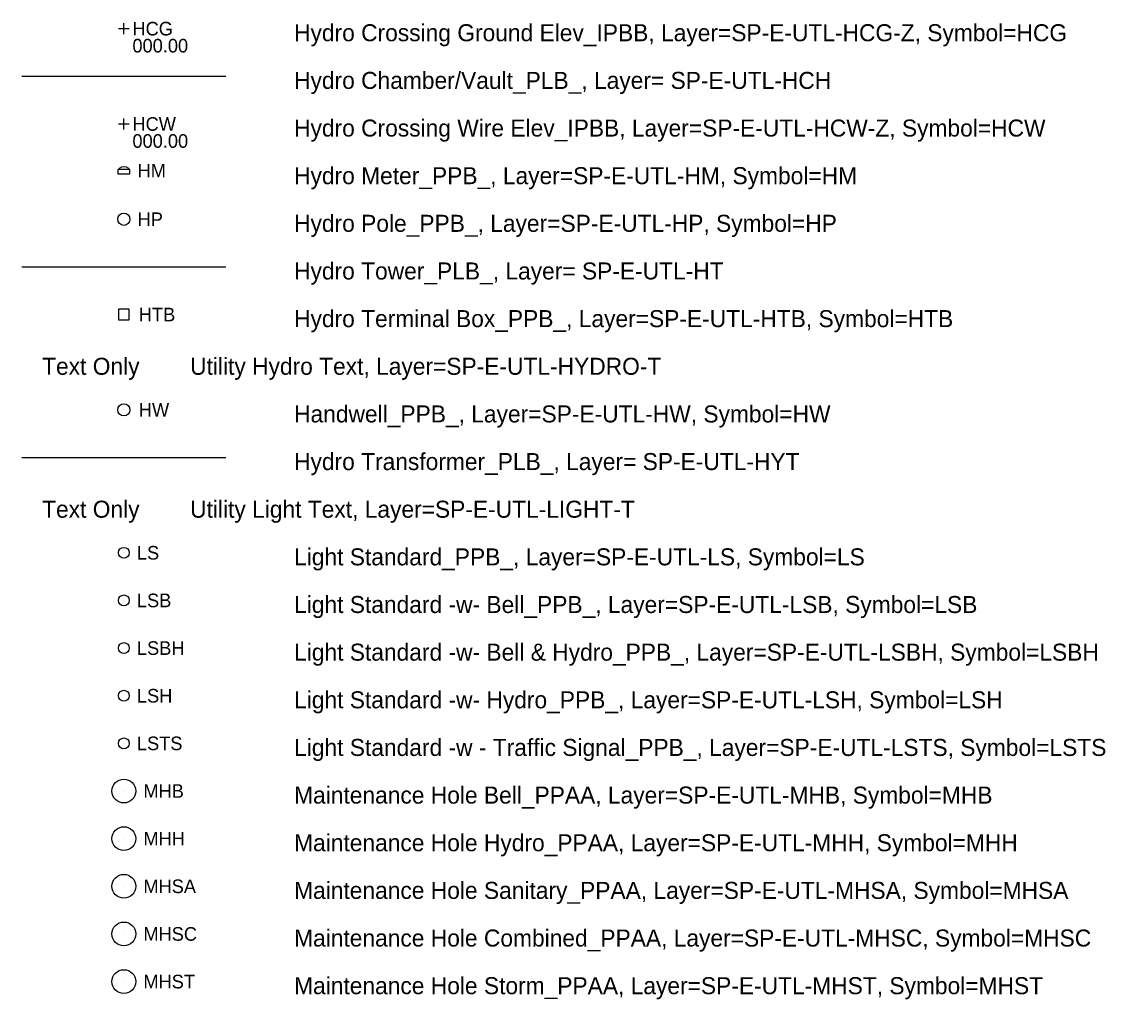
# Model space of a CAD drawing. Extents: x 500528 to 502626, y 4210261 to 4212624.
# Drawn here: x 501386.5 to 501545.7, y 4211000 to 4211143.6 of the extents above; entities that cross this region are included whole.
import ezdxf

# ---------------------------------------------------------------- set-up
doc = ezdxf.new("R2010")
doc.units = 0
for name, color, linetype in [('SP-E-UTL-BELL-T', 7, 'Continuous'), ('SP-E-UTL-COMB-T', 7, 'Continuous'), ('SP-E-UTL-HCG-Z', 7, 'Continuous'), ('SP-E-UTL-HCH', 7, 'Continuous'), ('SP-E-UTL-HCW-Z', 7, 'Continuous'), ('SP-E-UTL-HM', 7, 'Continuous'), ('SP-E-UTL-HP', 7, 'Continuous'), ('SP-E-UTL-HT', 7, 'Continuous'), ('SP-E-UTL-HTB', 7, 'Continuous'), ('SP-E-UTL-HW', 7, 'Continuous'), ('SP-E-UTL-HYDRO-T', 7, 'Continuous'), ('SP-E-UTL-HYT', 7, 'Continuous'), ('SP-E-UTL-LIGHT-T', 7, 'Continuous'), ('SP-E-UTL-LS', 7, 'Continuous'), ('SP-E-UTL-LSB', 7, 'Continuous'), ('SP-E-UTL-LSBH', 7, 'Continuous'), ('SP-E-UTL-LSH', 7, 'Continuous'), ('SP-E-UTL-LSTS', 7, 'Continuous'), ('SP-E-UTL-MHB', 7, 'Continuous'), ('SP-E-UTL-MHH', 7, 'Continuous'), ('SP-E-UTL-MHSA', 7, 'Continuous'), ('SP-E-UTL-MHSC', 7, 'Continuous'), ('SP-E-UTL-MHST', 7, 'Continuous'), ('SP-E-UTL-SAN-ST-COMB-T', 7, 'Continuous'), ('SP-E-UTL-SAN-T', 7, 'Continuous'), ('SP-E-UTL-STORM-T', 7, 'Continuous'), ('SP-E-UTL-T', 7, 'Continuous')]:
    doc.layers.add(name, color=color, linetype=linetype)

# ---------------------------------------------------------------- blocks, each defined once
blk = doc.blocks.new('HCG')
at = {"layer": 'SP-E-UTL-HCG-Z'}
for points in [[(-0.08, 0), (0.08, 0)], [(0, -0.08), (0, 0.08)]]:
    blk.add_lwpolyline(points, dxfattribs=at)
at = {"layer": 'SP-E-UTL-HYDRO-T'}
for s, p in [('HCG', (0.126, -0.1)), ('000.00', (0.126, -0.35))]:
    blk.add_text(s, height=0.2, dxfattribs=at).set_placement(p)
blk = doc.blocks.new('HCW')
at = {"layer": 'SP-E-UTL-HCW-Z'}
for points in [[(-0.08, 0), (0.08, 0)], [(0, -0.08), (0, 0.08)]]:
    blk.add_lwpolyline(points, dxfattribs=at)
at = {"layer": 'SP-E-UTL-HYDRO-T'}
for s, p in [('HCW', (0.126, -0.1)), ('000.00', (0.126, -0.35))]:
    blk.add_text(s, height=0.2, dxfattribs=at).set_placement(p)
blk = doc.blocks.new('HM')
at = {"layer": 'SP-E-UTL-HM'}
for p, q in [((-0.071, 0.048), (-0.071, 0.031)), ((0.071, 0.031), (0.071, 0.048))]:
    blk.add_line(p, q, dxfattribs=at)
blk.add_lwpolyline([(-0.09, -0.031), (0.09, -0.031), (0.09, 0.031), (-0.09, 0.031)], close=True, dxfattribs=at)
blk.add_arc((0, -0.049), 0.12, 53.7956, 126.2044, dxfattribs=at)
at = {"layer": 'SP-E-UTL-HYDRO-T'}
blk.add_text('HM', height=0.2, dxfattribs=at).set_placement((0.202, -0.086))
blk = doc.blocks.new('HP')
at = {"layer": 'SP-E-UTL-HP'}
blk.add_lwpolyline([(0, 0), (0, 0)], dxfattribs=at)
blk.add_circle((0, 0), 0.09, dxfattribs=at)
at = {"layer": 'SP-E-UTL-HYDRO-T'}
blk.add_text('HP', height=0.2, dxfattribs=at).set_placement((0.202, -0.1))
blk = doc.blocks.new('HTB')
at = {"layer": 'SP-E-UTL-HTB'}
for points in [[(-0.08, 0.08), (-0.08, -0.08), (0.08, -0.08), (0.08, 0.08), (-0.08, 0.08)], [(0, 0), (0, 0)]]:
    blk.add_lwpolyline(points, dxfattribs=at)
at = {"layer": 'SP-E-UTL-HYDRO-T'}
blk.add_text('HTB', height=0.2, dxfattribs=at).set_placement((0.22, -0.1))
blk = doc.blocks.new('HW')
at = {"layer": 'SP-E-UTL-HW'}
blk.add_lwpolyline([(0, 0), (0, 0)], dxfattribs=at)
blk.add_circle((0, 0), 0.09, dxfattribs=at)
at = {"layer": 'SP-E-UTL-T'}
blk.add_text('HW', height=0.2, dxfattribs=at).set_placement((0.22, -0.1))
blk = doc.blocks.new('LS')
at = {"layer": 'SP-E-UTL-LS'}
blk.add_lwpolyline([(0, 0), (0, 0)], dxfattribs=at)
blk.add_circle((0, 0), 0.08, dxfattribs=at)
at = {"layer": 'SP-E-UTL-LIGHT-T'}
blk.add_text('LS', height=0.2, dxfattribs=at).set_placement((0.192, -0.1))
blk = doc.blocks.new('LSB')
at = {"layer": 'SP-E-UTL-LSB'}
blk.add_lwpolyline([(0, 0), (0, 0)], dxfattribs=at)
blk.add_circle((0, 0), 0.08, dxfattribs=at)
at = {"layer": 'SP-E-UTL-COMB-T'}
blk.add_text('LSB', height=0.2, dxfattribs=at).set_placement((0.192, -0.1))
blk = doc.blocks.new('LSBH')
at = {"layer": 'SP-E-UTL-LSBH'}
blk.add_lwpolyline([(0, 0), (0, 0)], dxfattribs=at)
blk.add_circle((0, 0), 0.08, dxfattribs=at)
at = {"layer": 'SP-E-UTL-COMB-T'}
blk.add_text('LSBH', height=0.2, dxfattribs=at).set_placement((0.192, -0.1))
blk = doc.blocks.new('LSH')
at = {"layer": 'SP-E-UTL-LSH'}
blk.add_lwpolyline([(0, 0), (0, 0)], dxfattribs=at)
blk.add_circle((0, 0), 0.08, dxfattribs=at)
at = {"layer": 'SP-E-UTL-COMB-T'}
blk.add_text('LSH', height=0.2, dxfattribs=at).set_placement((0.192, -0.1))
blk = doc.blocks.new('LSTS')
at = {"layer": 'SP-E-UTL-LSTS'}
blk.add_lwpolyline([(0, 0), (0, 0)], dxfattribs=at)
blk.add_circle((0, 0), 0.08, dxfattribs=at)
at = {"layer": 'SP-E-UTL-COMB-T'}
blk.add_text('LSTS', height=0.2, dxfattribs=at).set_placement((0.192, -0.1))
blk = doc.blocks.new('MHB')
at = {"layer": 'SP-E-UTL-MHB'}
blk.add_lwpolyline([(0, 0), (0, 0)], dxfattribs=at)
blk.add_circle((0, 0), 0.175, dxfattribs=at)
at = {"layer": 'SP-E-UTL-BELL-T'}
blk.add_text('MHB', height=0.2, dxfattribs=at).set_placement((0.287, -0.1))
blk = doc.blocks.new('MHH')
at = {"layer": 'SP-E-UTL-MHH'}
blk.add_lwpolyline([(0, 0), (0, 0)], dxfattribs=at)
blk.add_circle((0, 0), 0.175, dxfattribs=at)
at = {"layer": 'SP-E-UTL-HYDRO-T'}
blk.add_text('MHH', height=0.2, dxfattribs=at).set_placement((0.287, -0.1))
blk = doc.blocks.new('MHSA')
at = {"layer": 'SP-E-UTL-MHSA'}
blk.add_lwpolyline([(0, 0), (0, 0)], dxfattribs=at)
blk.add_circle((0, 0), 0.175, dxfattribs=at)
at = {"layer": 'SP-E-UTL-SAN-T'}
blk.add_text('MHSA', height=0.2, dxfattribs=at).set_placement((0.287, -0.1))
blk = doc.blocks.new('MHSC')
at = {"layer": 'SP-E-UTL-MHSC'}
blk.add_lwpolyline([(0, 0), (0, 0)], dxfattribs=at)
blk.add_circle((0, 0), 0.175, dxfattribs=at)
at = {"layer": 'SP-E-UTL-SAN-ST-COMB-T'}
blk.add_text('MHSC', height=0.2, dxfattribs=at).set_placement((0.287, -0.1))
blk = doc.blocks.new('MHST')
at = {"layer": 'SP-E-UTL-MHST'}
blk.add_lwpolyline([(0, 0), (0, 0)], dxfattribs=at)
blk.add_circle((0, 0), 0.175, dxfattribs=at)
at = {"layer": 'SP-E-UTL-STORM-T'}
blk.add_text('MHST', height=0.2, dxfattribs=at).set_placement((0.287, -0.1))

msp = doc.modelspace()

# ---------------------------------------------------------------- linework, layer by layer
at = {"layer": 'SP-E-UTL-HCH'}
msp.add_line((501386.55, 4211135.59), (501416.55, 4211135.59), dxfattribs=at)
at = {"layer": 'SP-E-UTL-HT'}
msp.add_line((501386.55, 4211107.59), (501416.55, 4211107.59), dxfattribs=at)
at = {"layer": 'SP-E-UTL-HYT'}
msp.add_line((501386.55, 4211079.59), (501416.55, 4211079.59), dxfattribs=at)

# ---------------------------------------------------------------- block references
at = {"layer": 'SP-E-UTL-HCG-Z', "xscale": 10, "yscale": 10}
msp.add_blockref('HCG', (501401.55, 4211142.59), dxfattribs=at)
at = {"layer": 'SP-E-UTL-HCW-Z', "xscale": 10, "yscale": 10}
msp.add_blockref('HCW', (501401.55, 4211128.59), dxfattribs=at)
at = {"layer": 'SP-E-UTL-HM', "xscale": 10, "yscale": 10}
msp.add_blockref('HM', (501401.55, 4211121.59), dxfattribs=at)
at = {"layer": 'SP-E-UTL-HP', "xscale": 10, "yscale": 10}
msp.add_blockref('HP', (501401.55, 4211114.59), dxfattribs=at)
at = {"layer": 'SP-E-UTL-HTB', "xscale": 10, "yscale": 10}
msp.add_blockref('HTB', (501401.55, 4211100.59), dxfattribs=at)
at = {"layer": 'SP-E-UTL-HW', "xscale": 10, "yscale": 10}
msp.add_blockref('HW', (501401.55, 4211086.59), dxfattribs=at)
at = {"layer": 'SP-E-UTL-LS', "xscale": 10, "yscale": 10}
msp.add_blockref('LS', (501401.55, 4211065.59), dxfattribs=at)
at = {"layer": 'SP-E-UTL-LSB', "xscale": 10, "yscale": 10}
msp.add_blockref('LSB', (501401.55, 4211058.59), dxfattribs=at)
at = {"layer": 'SP-E-UTL-LSBH', "xscale": 10, "yscale": 10}
msp.add_blockref('LSBH', (501401.55, 4211051.59), dxfattribs=at)
at = {"layer": 'SP-E-UTL-LSH', "xscale": 10, "yscale": 10}
msp.add_blockref('LSH', (501401.55, 4211044.59), dxfattribs=at)
at = {"layer": 'SP-E-UTL-LSTS', "xscale": 10, "yscale": 10}
msp.add_blockref('LSTS', (501401.55, 4211037.59), dxfattribs=at)
at = {"layer": 'SP-E-UTL-MHB', "xscale": 10, "yscale": 10}
msp.add_blockref('MHB', (501401.55, 4211030.59), dxfattribs=at)
at = {"layer": 'SP-E-UTL-MHH', "xscale": 10, "yscale": 10}
msp.add_blockref('MHH', (501401.55, 4211023.59), dxfattribs=at)
at = {"layer": 'SP-E-UTL-MHSA', "xscale": 10, "yscale": 10}
msp.add_blockref('MHSA', (501401.55, 4211016.59), dxfattribs=at)
at = {"layer": 'SP-E-UTL-MHSC', "xscale": 10, "yscale": 10}
msp.add_blockref('MHSC', (501401.55, 4211009.59), dxfattribs=at)
at = {"layer": 'SP-E-UTL-MHST', "xscale": 10, "yscale": 10}
msp.add_blockref('MHST', (501401.55, 4211002.59), dxfattribs=at)

# ---------------------------------------------------------------- texts
at = {"layer": 'SP-E-UTL-HCG-Z'}
msp.add_text('Hydro Crossing Ground Elev_IPBB, Layer=SP-E-UTL-HCG-Z, Symbol=HCG ', height=2.5, dxfattribs=at).set_placement((501426.55, 4211140.74))
at = {"layer": 'SP-E-UTL-HCH'}
msp.add_text('Hydro Chamber/Vault_PLB_, Layer= SP-E-UTL-HCH ', height=2.5, dxfattribs=at).set_placement((501426.55, 4211133.74))
at = {"layer": 'SP-E-UTL-HCW-Z'}
msp.add_text('Hydro Crossing Wire Elev_IPBB, Layer=SP-E-UTL-HCW-Z, Symbol=HCW ', height=2.5, dxfattribs=at).set_placement((501426.55, 4211126.74))
at = {"layer": 'SP-E-UTL-HM'}
msp.add_text('Hydro Meter_PPB_, Layer=SP-E-UTL-HM, Symbol=HM ', height=2.5, dxfattribs=at).set_placement((501426.55, 4211119.74))
at = {"layer": 'SP-E-UTL-HP'}
msp.add_text('Hydro Pole_PPB_, Layer=SP-E-UTL-HP, Symbol=HP ', height=2.5, dxfattribs=at).set_placement((501426.55, 4211112.74))
at = {"layer": 'SP-E-UTL-HT'}
msp.add_text('Hydro Tower_PLB_, Layer= SP-E-UTL-HT ', height=2.5, dxfattribs=at).set_placement((501426.55, 4211105.74))
at = {"layer": 'SP-E-UTL-HTB'}
msp.add_text('Hydro Terminal Box_PPB_, Layer=SP-E-UTL-HTB, Symbol=HTB ', height=2.5, dxfattribs=at).set_placement((501426.55, 4211098.74))
at = {"layer": 'SP-E-UTL-HW'}
msp.add_text('Handwell_PPB_, Layer=SP-E-UTL-HW, Symbol=HW ', height=2.5, dxfattribs=at).set_placement((501426.55, 4211084.74))
at = {"layer": 'SP-E-UTL-HYDRO-T'}
msp.add_text('Text Only        Utility Hydro Text, Layer=SP-E-UTL-HYDRO-T', height=2.5, dxfattribs=at).set_placement((501389.55, 4211091.74))
at = {"layer": 'SP-E-UTL-HYT'}
msp.add_text('Hydro Transformer_PLB_, Layer= SP-E-UTL-HYT ', height=2.5, dxfattribs=at).set_placement((501426.55, 4211077.74))
at = {"layer": 'SP-E-UTL-LIGHT-T'}
msp.add_text('Text Only        Utility Light Text, Layer=SP-E-UTL-LIGHT-T', height=2.5, dxfattribs=at).set_placement((501389.55, 4211070.74))
at = {"layer": 'SP-E-UTL-LS'}
msp.add_text('Light Standard_PPB_, Layer=SP-E-UTL-LS, Symbol=LS ', height=2.5, dxfattribs=at).set_placement((501426.55, 4211063.74))
at = {"layer": 'SP-E-UTL-LSB'}
msp.add_text('Light Standard -w- Bell_PPB_, Layer=SP-E-UTL-LSB, Symbol=LSB ', height=2.5, dxfattribs=at).set_placement((501426.55, 4211056.74))
at = {"layer": 'SP-E-UTL-LSBH'}
msp.add_text('Light Standard -w- Bell & Hydro_PPB_, Layer=SP-E-UTL-LSBH, Symbol=LSBH ', height=2.5, dxfattribs=at).set_placement((501426.55, 4211049.74))
at = {"layer": 'SP-E-UTL-LSH'}
msp.add_text('Light Standard -w- Hydro_PPB_, Layer=SP-E-UTL-LSH, Symbol=LSH ', height=2.5, dxfattribs=at).set_placement((501426.55, 4211042.74))
at = {"layer": 'SP-E-UTL-LSTS'}
msp.add_text('Light Standard -w - Traffic Signal_PPB_, Layer=SP-E-UTL-LSTS, Symbol=LSTS ', height=2.5, dxfattribs=at).set_placement((501426.55, 4211035.74))
at = {"layer": 'SP-E-UTL-MHB'}
msp.add_text('Maintenance Hole Bell_PPAA, Layer=SP-E-UTL-MHB, Symbol=MHB ', height=2.5, dxfattribs=at).set_placement((501426.55, 4211028.74))
at = {"layer": 'SP-E-UTL-MHH'}
msp.add_text('Maintenance Hole Hydro_PPAA, Layer=SP-E-UTL-MHH, Symbol=MHH ', height=2.5, dxfattribs=at).set_placement((501426.55, 4211021.74))
at = {"layer": 'SP-E-UTL-MHSA'}
msp.add_text('Maintenance Hole Sanitary_PPAA, Layer=SP-E-UTL-MHSA, Symbol=MHSA ', height=2.5, dxfattribs=at).set_placement((501426.55, 4211014.74))
at = {"layer": 'SP-E-UTL-MHSC'}
msp.add_text('Maintenance Hole Combined_PPAA, Layer=SP-E-UTL-MHSC, Symbol=MHSC ', height=2.5, dxfattribs=at).set_placement((501426.55, 4211007.74))
at = {"layer": 'SP-E-UTL-MHST'}
msp.add_text('Maintenance Hole Storm_PPAA, Layer=SP-E-UTL-MHST, Symbol=MHST ', height=2.5, dxfattribs=at).set_placement((501426.55, 4211000.74))

doc.saveas('drawing.dxf')
